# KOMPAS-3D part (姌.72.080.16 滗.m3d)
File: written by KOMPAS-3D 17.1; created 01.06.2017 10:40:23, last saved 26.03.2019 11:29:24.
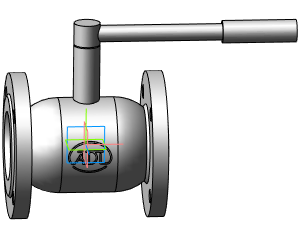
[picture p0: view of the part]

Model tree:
1. Операция без истории:3  (labels: Сталь 20  ГОСТ 1050-88)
